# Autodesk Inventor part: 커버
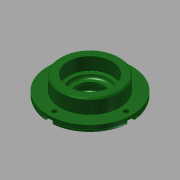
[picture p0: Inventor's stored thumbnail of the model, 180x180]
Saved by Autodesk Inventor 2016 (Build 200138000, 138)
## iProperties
Company: 한국ATC센터
Created: 2016-04
Part Number: 커버
Document SubType Name: Modeling
Designer: mdu
Density: 7.86 g/cm^3
Mass: 351.567 g
Surface Area: 161.165 cm^2
Volume: 44.7286 cm^3
Material: 강철, 연강
Appearance: 진녹색
Author: mdu
Revision Number: 1
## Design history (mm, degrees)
sketch "스케치1"
  geometry: C1 r 38 at (0, 0); 1 further point
  constraints: 1 centre point, 1 coincident
  dimensions: "d0" = 76 diameter of C1
extrude "돌출1" new body sketch "스케치1" distance "d1" = 7; taper "d2" = 0 deg
sketch "스케치2"
  geometry: C1 r 27 at (0, 0); 1 further point
  constraints: 1 centre point, 1 coincident
  dimensions: "d3" = 54 diameter of C1
extrude "돌출2" join sketch "스케치2" distance "d4" = 13; taper "d5" = 0 deg
sketch "스케치3"
  geometry: C1 r 20 at (0, 0); 1 further point
  constraints: 1 centre point, 1 coincident
  dimensions: "d6" = 40 diameter of C1
extrude "돌출3" join sketch "스케치3" distance "d7" = 5; taper "d8" = 0 deg
hole "구멍1" diameter "d11" = 25; stored, may be unused: countersink angle "d15" = 90 deg, drill point angle "d17" = 118 deg; dims "d9" = 10, "d10" = 10, "d12" = 6, "d13" = 32, "d14" = 8.3, "d16" = 8
hole "구멍2" diameter "d20" = 34; stored, may be unused: countersink angle "d24" = 90 deg, drill point angle "d26" = 0 deg; dims "d18" = 10, "d19" = 10, "d21" = 6, "d22" = 40, "d23" = 12, "d25" = 3
fillet "모깎기2" dims "d34" = 3
fillet "모깎기1" dims "d27" = 0.3
chamfer "모따기1" distance "d28" = 1; stored, may be unused: second distance "d29" = 2, angle "d30" = 45 deg
chamfer "모따기2" distance "d31" = 1.2; stored, may be unused: second distance "d32" = 2, angle "d33" = 30 deg
sketch "스케치4" dims "d35" = 65
  geometry: 3 further points
  constraints: 2 horizontal alignment, 1 coincident, 2 other
hole "구멍3" sketch "스케치4" at (32.5, 0) diameter "d36" = 4.5; stored, may be unused: countersink angle "d40" = 90 deg, drill point angle "d42" = 118 deg; dims "d37" = 6, "d38" = 8, "d39" = 4.4, "d41" = 13
sketch "스케치5"
  geometry: L1 (0, 4)-(5.5, 4); L2 (5.5, 4)-(5.5, -4); L3 (5.5, -4)-(0, -4); L4 (0, -4)-(0, 4); C1 r 2.25 at (0, 0) reference; C2 r 38 at (-32.5, 0) reference; 2 further points
  constraints: 8 end point, 3 horizontal, 2 parallel, 1 perpendicular, 1 tangent, 1 vertical alignment, 1 other
extrude "돌출4" cut sketch "스케치5" stored distance "d47" = 24.5; taper "d48" = 0 deg
node "솔리드1"
pattern_circular "원형 패턴1" dims angle "d44" = 360 deg
pattern_circular "원형 패턴2" dims angle "d50" = 360 deg
node "투영된 루프1"
